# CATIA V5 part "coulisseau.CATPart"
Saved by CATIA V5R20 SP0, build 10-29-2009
Part number: coulisseau
Bounding box of the stored display mesh (mm): x -5.992 to 5.992, y -5.656 to 5.656, z -5.992 to 5.992
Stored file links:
  D:\Dropbox\IAO_2011\MMS_GR1\dwalter\dwalter\CATIA\coulisseau.CATPart
  D:\Dropbox\IAO_2011\MMS_GR1\dwalter\dwalter\CATIA\dwalter.CATProduct
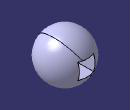
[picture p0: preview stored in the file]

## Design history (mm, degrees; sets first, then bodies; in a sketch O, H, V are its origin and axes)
Set1
  Plane1: linked copy from another document
  Point1: linked copy from another document
  Line1: linked copy from another document
  Plane2: linked copy from another document
Body1 (main body)
  Sketch1 on Plane1, origin (0, 0, 0), H (0, 1, 0), V (0, 0, 1)
    arc A1 centre (0, 0) radius 6 from (6, 0) to (-6, 0) ccw
    point P1 (0, 0)
    point P2 (6, 0)
    point P3 (-6, 0)
    reference projected point E1 (0, 0) from Point1
    line L1 (6, 0) -> (-6, 0)
    radius A1 = 6
    coincidence: P1 E1, L1 H
    horizontal: L1 H
    symmetry: P3 P2 V
  Shaft1: profile Sketch1, axis Line1, angle 360
  Sketch2 on Plane2, origin (0, 0, 0), H (-1, 0, 0), V (0, 0, 1)
    line L1 (-2, 2) -> (2, 2)
    line L2 (2, 2) -> (2, -2)
    line L3 (2, -2) -> (-2, -2)
    line L4 (-2, -2) -> (-2, 2)
    reference projected point E1 (0, 0) from edge
    reference projected point E2 (0, 0) from edge
    distance L1 E1 = 2
    distance L2 E2 = 2
    horizontal: L1 H, L3 H
    vertical: L2 V, L4 V
    symmetry: L2 L4 V, L3 L1 H
  Pocket1: profile Sketch2, direction (0, -1, 0), through (limit type 3), opposite side length 20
